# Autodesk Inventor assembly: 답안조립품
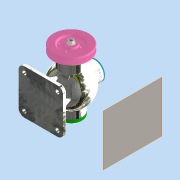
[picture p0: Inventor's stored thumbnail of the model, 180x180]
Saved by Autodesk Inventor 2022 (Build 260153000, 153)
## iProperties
Created: 2024-04
Part Number: 답안조립품
Document SubType Name: Assembly
Designer: Admin
Author: Admin
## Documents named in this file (16)
- C:\Users\Admin\Desktop\740406V1002\답안조립품.iam
- C:\Users\Admin\Desktop\740406V1002\본체.ipt
- C:\Users\Admin\Desktop\740406V1002\부품\앞커버.ipt
- C:\Users\Admin\Desktop\740406V1002\부품\뒤커버.ipt
- C:\Users\Admin\Desktop\740406V1002\부품\베어링- 6202.ipt
- KS B 2023 - 6202 - 15 x 35 x 11 - 7.8.ipt
- C:\Users\Admin\Desktop\740406V1002\부품\칼라.ipt
- C:\Users\Admin\Desktop\740406V1002\부품\편심축.ipt
- C:\Users\Admin\Desktop\740406V1002\부품\볼트 M4 x 16.ipt
- C:\Users\Admin\Desktop\740406V1002\부품\키 4 x 4 x 12.ipt
- C:\Users\Admin\Desktop\740406V1002\부품\V-벨트풀리.ipt
- C:\Users\Admin\Desktop\740406V1002\부품\너트 M8.ipt
- C:\Users\Admin\Desktop\740406V1002\부품\슬라이드.ipt
- C:\Users\Admin\Desktop\740406V1002\부품\상부커버.ipt
- C:\Users\Admin\Desktop\740406V1002\부품\오일실 15 30 7.ipt
- C:\Users\Admin\Desktop\740406V1002\부품\볼트 M4 x 12.ipt
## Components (15 placed, 4 different names)
1. KS B 2023 - 6202 - 15 x 35 x 11 - 7.8:1
2. KS B 2023 - 6202 - 15 x 35 x 11 - 7.8:2
3. ISO 4762 M4 x 16:1
4. ISO 4762 M4 x 16:2
5. ISO 4762 M4 x 16:3
6. ISO 4762 M4 x 16:4
7. ISO 4762 M4 x 16:5
8. ISO 4762 M4 x 16:6
9. ISO 4762 M4 x 16:7
10. ISO 4762 M4 x 16:8
11. V-벨트풀리:1
12. KS B 1021 - 에 따름 ISO 1207 - 미터 A  M 4 x 12:1
13. KS B 1021 - 에 따름 ISO 1207 - 미터 A  M 4 x 12:2
14. KS B 1021 - 에 따름 ISO 1207 - 미터 A  M 4 x 12:3
15. KS B 1021 - 에 따름 ISO 1207 - 미터 A  M 4 x 12:4
